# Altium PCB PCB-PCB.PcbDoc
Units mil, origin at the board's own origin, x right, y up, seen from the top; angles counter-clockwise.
Board outline 3937.01 x 1771.65 mil, 2 copper layers (Top Layer, Bottom Layer); 15 components, 36 nets, 117 pads, 7 vias.
Unrouted connection lines stored in the file: 2.
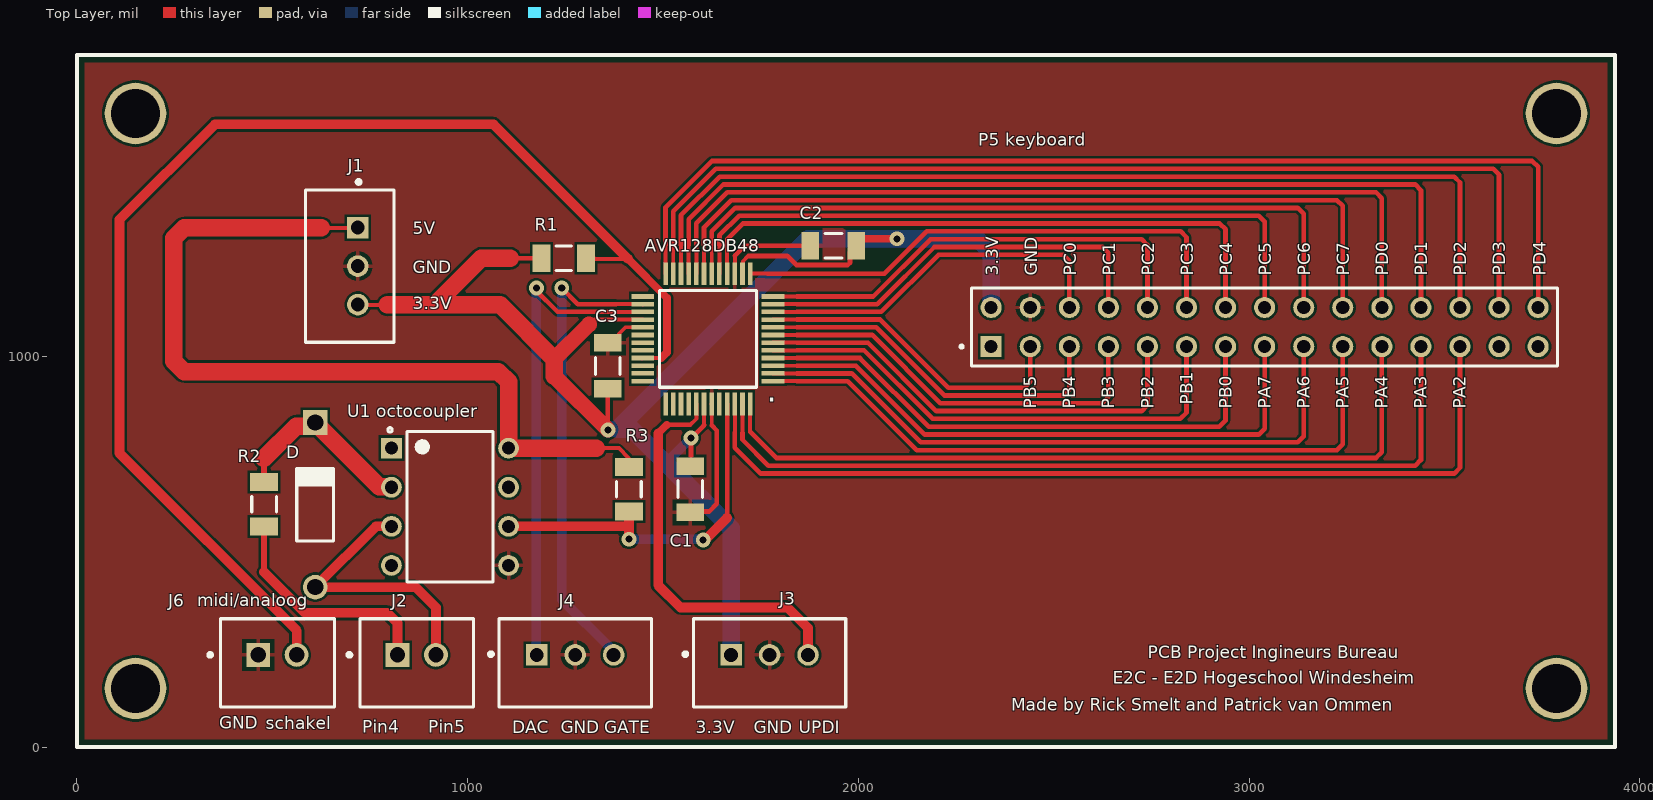
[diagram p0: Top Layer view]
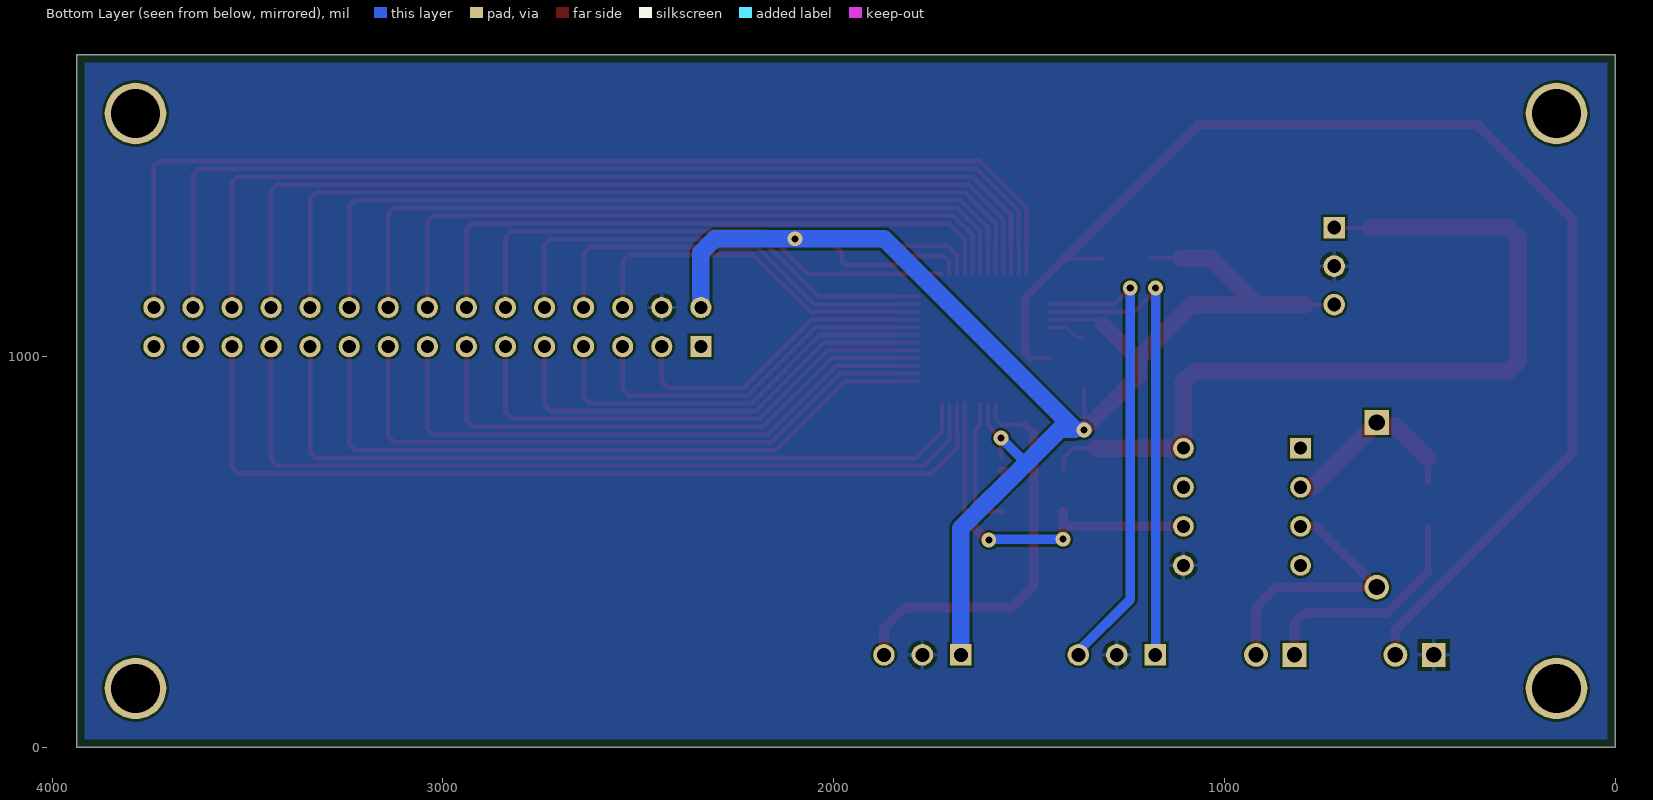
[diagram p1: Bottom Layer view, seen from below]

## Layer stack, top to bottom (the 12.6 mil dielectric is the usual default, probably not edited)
Top Solder: solder mask 0.4, Solder Resist, Dk 3.5
Top Layer: signal copper 1.4
Dielectric 1: dielectric 12.6, FR-4, Dk 4.8
Bottom Layer: signal copper 1.4
Bottom Solder: solder mask 0.4, Solder Resist, Dk 3.5

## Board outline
0,0 0,1771.65 3937.01,1771.65 3937.01,0

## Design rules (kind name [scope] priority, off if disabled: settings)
Clearance [All] p1: gap=6 ignorepadtopadclearanceinfootprint=TRUE
HoleSize [All] p1: absolutevalues=TRUE maxlimit=220.47 minlimit=12 maxpercent=80.000 minpercent=20.000
HoleToHoleClearance [All] p1: gap=12 allowstackedmicrovias=FALSE
MinimumAnnularRing [All] p1: minimumring=8
MinimumSolderMaskSliver [All] p1: minsoldermaskwidth=6
PolygonConnect [All] p1: connectstyle=Relief reliefconductorwidth=10 reliefentries=4 polygonreliefangle="90 Angle" airgapwidth=10
RoutingVias [All] p1: holewidth=18 width=26 viastyle="Through Hole" minholewidth=12 minwidth=26 maxholewidth=18 maxwidth=50
SilkToSolderMaskClearance [IsPad] p1: minsilkscreentomaskgap=6 clearancetoexposedcopper=TRUE
SolderMaskExpansion [All] p1: expansion=4 istentingtop=FALSE
SupplyNets "Schematic Supply Nets_1" [InNet('GND')] p1: voltage=0.000
Width [All] p1: maxlimit=45 minlimit=8 preferedwidth=10
26 further rules are at their usual default settings.

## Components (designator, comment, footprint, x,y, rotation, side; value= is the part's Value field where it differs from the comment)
AVR128DB48 "AVR128DB48-I_PT" QFP50P900X900X120-48N 1615,1045 r180 top
C1 "100nF" C1206 1570,660 r90 top
C2 "100nF" C1206 1936,1283 r0 top
C3 "100nF" C1206 1359,976 r270 top
D "IN4007" DIOAD1070W78L470D235P 610,620 r270 top
J1 "B3B-XH-A(LF)(SN)" FP-B3B-XH-A_LF_SN-MFG 698.33,1231 r270 top
J2 "B2B-XH-A(LF)(SN)" FP-B2B-XH-A_LF_SN-MFG 869.79,215.33 r0 top
J3 "B3B-XH-A(LF)(SN)" FP-B3B-XH-A_LF_SN-MFG 1773,215.33 r0 top
J4 "B3B-XH-A(LF)(SN)" FP-B3B-XH-A_LF_SN-MFG 1275.43,215.33 r0 top
J6 "B2B-XH-A(LF)(SN)" FP-B2B-XH-A_LF_SN-MFG 513.21,215.33 r0 top
"P5 keyboard" "TSW-115-14-S-D" SAMTEC_TSW-115-14-S-D 2340,1025 r0 top
R1 "10k" R1206 1246,1251 r0 top
R2 "220" R1206 479,621.48 r90 top
R3 "1K" R1206 1413,660 r270 top
"U1 octocoupler" "6N139VM" DIP762W50P254L977H451Q8 955,615 r0 top

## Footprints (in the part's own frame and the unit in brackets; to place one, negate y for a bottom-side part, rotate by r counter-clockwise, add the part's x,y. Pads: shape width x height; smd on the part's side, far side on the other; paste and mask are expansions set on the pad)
C1206 [mm] "Chip Capacitor, Body 3.2x1.6mm, Height 1.7mm, IPC Medium Density"
  rect 1.15x1.8 smd: 1(-1.5,0) 2(1.5,0)
  silkscreen extent -0.55,-0.8 0.55,0.8, body extent -1.7,-0.9 1.7,0.9, height 1.7
DIOAD1070W78L470D235P [mm]
  round 1.6 hole 1.05: A(5.35,0)
  rect 1.6x1.6 hole 1.05: C(-5.35,0)
  silkscreen extent -2.4,-1.2 2.35,1.2
DIP762W50P254L977H451Q8 [mm]
  rect 1.35x1.35 hole 0.85: 1(-3.81,3.81)
  round 1.35 hole 0.85: 2(-3.81,1.27) 3(-3.81,-1.27) 4(-3.81,-3.81) 5(3.81,-3.81) 6(3.81,-1.27) 7(3.81,1.27) 8(3.81,3.81)
  silkscreen extent -4.04,-4.9 2.8,5.14
FP-B2B-XH-A_LF_SN-MFG [mm]
  rect 1.55x1.55 hole 1 paste-2539.97 mask+0: 1(-1.25,0.525)
  round 1.55 hole 1 paste-2539.97 mask+0: 2(1.25,0.525)
  silkscreen extent -4.5,-2.88 3.7,2.88, body extent -3.8,-2.98 3.8,2.98, height 0.25
FP-B3B-XH-A_LF_SN-MFG [mm]
  rect 1.4x1.4 hole 0.9 paste-2539.97 mask+0: 1(-2.5,0.525)
  round 1.4 hole 0.9 paste-2539.97 mask+0: 2(0,0.525) 3(2.5,0.525)
  silkscreen extent -5.6,-2.88 4.95,2.88, body extent -5.05,-2.98 5.05,2.98, height 0.25
QFP50P900X900X120-48N [mm]
  rect 1.475x0.3 smd: 1(-4.238,2.75) 2(-4.238,2.25) 3(-4.238,1.75) 4(-4.238,1.25) 5(-4.238,0.75) 6(-4.238,0.25) 7(-4.238,-0.25) 8(-4.238,-0.75) 9(-4.238,-1.25) 10(-4.238,-1.75) 11(-4.238,-2.25) 12(-4.238,-2.75) 25(4.238,-2.75) 26(4.238,-2.25) 27(4.238,-1.75) 28(4.238,-1.25) 29(4.238,-0.75) 30(4.238,-0.25) 31(4.238,0.25) 32(4.238,0.75) 33(4.238,1.25) 34(4.238,1.75) 35(4.238,2.25) 36(4.238,2.75)
  rect 0.3x1.475 smd: 13(-2.75,-4.238) 14(-2.25,-4.238) 15(-1.75,-4.238) 16(-1.25,-4.238) 17(-0.75,-4.238) 18(-0.25,-4.238) 19(0.25,-4.238) 20(0.75,-4.238) 21(1.25,-4.238) 22(1.75,-4.238) 23(2.25,-4.238) 24(2.75,-4.238) 37(2.75,4.238) 38(2.25,4.238) 39(1.75,4.238) 40(1.25,4.238) 41(0.75,4.238) 42(0.25,4.238) 43(-0.25,4.238) 44(-0.75,4.238) 45(-1.25,4.238) 46(-1.75,4.238) 47(-2.25,4.238) 48(-2.75,4.238)
  silkscreen extent -3.15,-3.15 3.15,3.15
R1206 [mm] "Chip Resistor, Body 3.2x1.6mm, IPC Medium Density"
  rect 1.15x1.8 smd: 1(-1.45,0) 2(1.45,0)
  silkscreen extent -0.5,-0.8 0.5,0.8, body extent -1.67,-0.87 1.67,0.87, height 0.75
SAMTEC_TSW-115-14-S-D [mm]
  rect 1.37x1.37 hole 0.85: 01(0,0)
  round 1.37 hole 0.85: 02(0,2.54) 03(2.54,0) 04(2.54,2.54) 05(5.08,0) 06(5.08,2.54) 07(7.62,0) 08(7.62,2.54) 09(10.16,0) 10(10.16,2.54) 11(12.7,0) 12(12.7,2.54) 13(15.24,0) 14(15.24,2.54) 15(17.78,0) 16(17.78,2.54) 17(20.32,0) 18(20.32,2.54) 19(22.86,0) 20(22.86,2.54) 21(25.4,0) 22(25.4,2.54) 23(27.94,0) 24(27.94,2.54) 25(30.48,0) 26(30.48,2.54) 27(33.02,0) 28(33.02,2.54) 29(35.56,0) 30(35.56,2.54)
  silkscreen extent -2.02,-1.27 36.83,3.81

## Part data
AVR128DB48: "AVR AVRÂ® DB Microcontroller IC 8-Bit 24MHz 128KB (128K x 8) FLASH 48-TQFP (7x7)", Package=None
C1 C2 C3: library part Capacitor_1206, "SMD Capacitor 1206"
D: "Diode Standard 1000V 1A Through Hole DO-204AL _DO-41_", Package="DO-41 Vishay"
J1 J3 J4: library part CMP-17439-000014-3, "CONN HEADER VERT 3POS 2.5MM", Color=Natural, Contact Resistance=20mR, Current Rating=3A, Flammability Rating="UL94 V-0", Housing Color=White, Insulation Resistance=1GR, Max Operating Temperature=85°C, Max Voltage Rating (AC)=250V, Min Operating Temperature=-25°C
J2 J6: library part CMP-2000-05888-3, "CONN HEADER VERT 2POS 2.5MM", Color=Natural, Contact Resistance=20mR, Current Rating=3A, Housing Color=White, Insulation Resistance=1GR, Max Operating Temperature=85°C, Max Voltage Rating (AC)=250V, Min Operating Temperature=-25°C
"P5 keyboard": Package=None
R1 R2 R3: library part Resistor_1206, "SMD Resistor 1206"
"U1 octocoupler": "High Speed Optocoupler, 100 kBd, Low Input Current, Photodiode Darlington Output", Package=None

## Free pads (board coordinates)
  round 157.48 hole 125.98: 2(3787.01,1621.65) 3(3787.01,150) 4(150,150) 5(150,1621.65)

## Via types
v1: diameter 38, hole 18, Top Layer to Bottom Layer, 7 vias

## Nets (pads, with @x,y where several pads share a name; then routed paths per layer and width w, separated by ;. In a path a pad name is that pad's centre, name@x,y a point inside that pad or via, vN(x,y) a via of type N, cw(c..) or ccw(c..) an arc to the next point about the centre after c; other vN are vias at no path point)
GND: "P5 keyboard.04" "U1 octocoupler.5" AVR128DB48.15 AVR128DB48.29 AVR128DB48.43 C1.1 C2.1 C3.1 J1.2 J3.2 J4.2 J6.1 | length 686.1
  Top Layer w8: C3.1@1363,1043.63 1368.73,1049.36 1379.36,1049.36 C3.1@1386.86,1056.86
  Top Layer w10: C3.1@1386.86,1056.86 1404.53,1074.53 AVR128DB48.29 ; 1624.84,823.16 AVR128DB48.43 ; AVR128DB48.15 1683.9,1257.58
  Top Layer w12: C1.1@1567.94,603 1618,603 1637.73,622.73 1637.73,810.27 1624.84,823.16 ; AVR128DB48.43 AVR128DB48.43@1624.94,878.06 ; 1683.9,1257.58 1709.31,1283 C2.1
NetAVR128DB48_1: "P5 keyboard.19" AVR128DB48.1 | length 1787.6
  Top Layer w10: AVR128DB48.1 1843,936.73
  Top Layer w12: 1843,936.73 1973.27,936.73 2150,760 3225,760 3240,775 3240,1025
NetAVR128DB48_2: "P5 keyboard.17" AVR128DB48.2 | length 1667.4
  Top Layer w10: AVR128DB48.2 1843,956.42
  Top Layer w12: 1843,956.42 1983.58,956.42 2160,780 3125,780 3140,795 3140,1025
NetAVR128DB48_3: "P5 keyboard.15" AVR128DB48.3 | length 1547.3
  Top Layer w10: AVR128DB48.3 1843,976.1
  Top Layer w12: 1843,976.1 1993.9,976.1 2170,800 3025,800 3040,815 3040,1025
NetAVR128DB48_4: "P5 keyboard.13" AVR128DB48.4 | length 1426.6
  Top Layer w10: AVR128DB48.4 1843,995.79
  Top Layer w12: 1843,995.79 2004.21,995.79 2180,820 2924,820 2940,836 2940,1025
NetAVR128DB48_5: "P5 keyboard.11" AVR128DB48.5 | length 1306.5
  Top Layer w10: AVR128DB48.5 1843,1015.47
  Top Layer w12: 1843,1015.47 2014.53,1015.47 2190,840 2824,840 2840,856 2840,1025
NetAVR128DB48_6: "P5 keyboard.09" AVR128DB48.6 | length 1186.9
  Top Layer w10: AVR128DB48.6 1843,1035.16
  Top Layer w12: 1843,1035.16 2024.84,1035.16 2200,860 2725,860 2740,875 2740,1025
NetAVR128DB48_7: "P5 keyboard.07" AVR128DB48.7 | length 1066.2
  Top Layer w10: AVR128DB48.7 1843,1054.84
  Top Layer w12: 1843,1054.84 2035.16,1054.84 2210,880 2624,880 2640,896 2640,1025
NetAVR128DB48_8: "P5 keyboard.05" AVR128DB48.8 | length 946.7
  Top Layer w10: AVR128DB48.8 1843,1074.53
  Top Layer w12: 1843,1074.53 2045.47,1074.53 2220,900 2525,900 2540,915 2540,1025
NetAVR128DB48_9: "P5 keyboard.03" AVR128DB48.9 | length 826.5
  Top Layer w10: AVR128DB48.9 1843,1094.21
  Top Layer w12: 1843,1094.21 2055.79,1094.21 2230,920 2425,920 2440,935 2440,1025
NetAVR128DB48_10: "P5 keyboard.06" AVR128DB48.10 | length 945.2
  Top Layer w10: AVR128DB48.10 1843,1113.9
  Top Layer w12: 1843,1113.9 2058.9,1113.9 2205.34,1260.34 2524.66,1260.34 2540,1245 2540,1125
NetAVR128DB48_11: "P5 keyboard.08" AVR128DB48.11 | length 1065
  Top Layer w10: AVR128DB48.11 1843,1133.58
  Top Layer w12: 1843,1133.58 2048.58,1133.58 2195,1280 2625,1280 2640,1265 2640,1125
NetAVR128DB48_12: "P5 keyboard.10" AVR128DB48.12 | length 1185.1
  Top Layer w10: AVR128DB48.12 1843,1153.27
  Top Layer w12: 1843,1153.27 2038.27,1153.27 2185,1300 2725,1300 2740,1285 2740,1125
NetAVR128DB48_13: "P5 keyboard.12" AVR128DB48.13 | length 1347.7
  Top Layer w10: AVR128DB48.13 1767,1211.85
  Top Layer w12: 1767,1211.85 2066.85,1211.85 2175,1320 2825,1320 2840,1305 2840,1125
NetAVR128DB48_14: "P5 keyboard.02" AVR128DB48.14 AVR128DB48.28 AVR128DB48.42 C1.2 C2.2 C3.2 J1.3 J3.1 R1.1 | length 4299.6
  Top Layer w8: 1082.78,1132.22 1084.67,1130.33
  Top Layer w10: J1.3@709,1132 795,1132 ; 1310.64,1081.64 1311.82,1081.64 1324.39,1094.21 1376.92,1094.21 AVR128DB48.28 ; 1605.16,824.16 AVR128DB48.42 ; AVR128DB48.14 1704.49,1212.76 1704.49,1243.57 1717.92,1257 ; C2.2@1978.91,1266.86 C2.2
  Top Layer w12: 1109,1251 R1.1 ; v1(1359,812) C3.2 ; 1572,744 v1(1572,791) 1605.16,824.16 ; 1717.92,1257 1818,1257 1841,1234 1949.15,1234 1973.06,1234 1978.91,1239.86 C2.2@1978.91,1266.86
  Top Layer w20: C1.2@1557.36,706.42 1568.42,706.42 C1.2@1570,708 ; C2.2 1995.06,1288.36 2007.69,1301 v1(2099,1301)
  Top Layer w40: 1222,949 v1(1359,812) ; 1222,993 1310.64,1081.64
  Top Layer w45: 795,1132 795.33,1132.33 916.33,1132.33 ; 1082.89,1132.33 916.33,1132.33 ; 1084.67,1130.33 1222,993 1222,949 ; 1109,1251 1035,1251 916.33,1132.33
  Bottom Layer w12: 1507.43,726.57 1507.57,726.57
  Bottom Layer w25: 1507.57,726.57 v1(1572,791)
  Bottom Layer w40: v1(1359,812) 1360.15,813.15 1383.15,813.15
  Bottom Layer w45: J3.1@1676,241.06 1674.57,241.06 1674.57,560.43 1595,640 1594,640 1507.43,726.57 1420.85,813.15 1383.15,813.15 1871,1301 v1(2099,1301) 2304,1301 2340,1265 2340,1125
NetAVR128DB48_16: "P5 keyboard.14" AVR128DB48.16 | length 1586.8
  Top Layer w10: AVR128DB48.16 1664.21,1285
  Top Layer w12: 1664.21,1285 1664.21,1300.21 1704,1340 2925,1340 2940,1325 2940,1125
NetAVR128DB48_17: "P5 keyboard.16" AVR128DB48.17 | length 1740.3
  Top Layer w10: AVR128DB48.17 1644.53,1285
  Top Layer w12: 1644.53,1285 1644.53,1309.53 1695,1360 3025,1360 3040,1345 3040,1125
NetAVR128DB48_18: "P5 keyboard.18" AVR128DB48.18 | length 1894.3
  Top Layer w10: AVR128DB48.18 1624.84,1285
  Top Layer w12: 1624.84,1285 1624.84,1319.84 1685,1380 3125,1380 3140,1365 3140,1125
NetAVR128DB48_19: "P5 keyboard.20" AVR128DB48.19 | length 2048.3
  Top Layer w10: AVR128DB48.19 1605.16,1285
  Top Layer w12: 1605.16,1285 1605.16,1330.16 1675,1400 3225,1400 3240,1385 3240,1125
NetAVR128DB48_20: "P5 keyboard.22" AVR128DB48.20 | length 2202.3
  Top Layer w10: AVR128DB48.20 1585.47,1285
  Top Layer w12: 1585.47,1285 1585.47,1340.47 1665,1420 3325,1420 3340,1405 3340,1125
NetAVR128DB48_21: "P5 keyboard.24" AVR128DB48.21 | length 2356.3
  Top Layer w10: AVR128DB48.21 1565.79,1285
  Top Layer w12: 1565.79,1285 1565.79,1350.79 1655,1440 3425,1440 3440,1425 3440,1125
NetAVR128DB48_22: "P5 keyboard.26" AVR128DB48.22 | length 2510.3
  Top Layer w10: AVR128DB48.22 1546.1,1285
  Top Layer w12: 1546.1,1285 1546.1,1361.1 1645,1460 3525,1460 3540,1445 3540,1125
NetAVR128DB48_23: "P5 keyboard.28" AVR128DB48.23 | length 2664.3
  Top Layer w10: AVR128DB48.23 1526.42,1285
  Top Layer w12: 1526.42,1285 1526.42,1371.42 1635,1480 3625,1480 3640,1465 3640,1125
NetAVR128DB48_24: "P5 keyboard.30" AVR128DB48.24 | length 2818.4
  Top Layer w10: AVR128DB48.24 1506.73,1285
  Top Layer w12: 1506.73,1285 1506.73,1381.73 1625,1500 3725,1500 3740,1485 3740,1125
NetAVR128DB48_26: AVR128DB48.26 J4.3 | length 1210
  Top Layer w10: 1380.6,1133.58 AVR128DB48.26
  Top Layer w12: v1(1241,1175) 1282.41,1133.59 1380.59,1133.59 ; AVR128DB48.26@1448.06,1133.68 AVR128DB48.26
  Bottom Layer w25: v1(1241,1175) 1241,377.85 1368.09,250.76 1368.09,249.91 1373,245 J4.3@1373.85,245
NetAVR128DB48_27: AVR128DB48.27 J4.1 | length 1241
  Top Layer w10: 1373.9,1113.9 AVR128DB48.27
  Top Layer w12: v1(1176,1175) 1176,1168 1230.1,1113.9 1373.9,1113.9
  Bottom Layer w12: J4.1@1176,237 J4.1
  Bottom Layer w25: J4.1@1176,237 v1(1176,1175)
NetAVR128DB48_33: AVR128DB48.33 J6.2 R1.2 | length 3298.3
  Top Layer w8: R1.2@1321,1251 R1.2@1322.4,1249.6 ; AVR128DB48.33@1446.24,993.88 AVR128DB48.33
  Top Layer w10: R1.2@1310,1251 1321,1251 R1.2@1324.86,1251 ; R1.2@1322.4,1249.6 1410.4,1249.6 ; AVR128DB48.33 1495.79,995.79
  Top Layer w20: 1410.4,1249.6 1510,1150 1510,1010 1495.79,995.79
  Top Layer w25: J6.2@563,241 563,298 109,752 109,1350 353,1594 1066,1594 1410.4,1249.6
NetAVR128DB48_41: AVR128DB48.41 J3.3 | length 1037
  Top Layer w10: 1569.69,824.69 1585.47,840.47 AVR128DB48.41
  Top Layer w12: 1509.69,824.69 1569.69,824.69
  Top Layer w20: 1488,803 1509.69,824.69
  Top Layer w25: 1488,803 1488,414 1545,357 1819,357 1871.43,304.57 J3.3
NetAVR128DB48_45: "U1 octocoupler.6" AVR128DB48.45 R3.2 | length 982.6
  Top Layer w12: 1411,565 1413,567 R3.2 ; 1664.21,586.79 AVR128DB48.45
  Top Layer w25: 1105,565 1411,565 ; v1(1413,532) 1413,567 R3.2 ; v1(1603,530) 1606.52,530 1613.02,536.5 1613.93,536.5 1664.21,586.79
  Bottom Layer w12: v1@1601,532 v1(1603,530)
  Bottom Layer w25: v1(1413,532) v1@1601,532
NetAVR128DB48_46: "P5 keyboard.25" AVR128DB48.46 | length 2311.7
  Top Layer w10: 1683.9,805 AVR128DB48.46
  Top Layer w12: 1683.9,805 1683.9,766.1 1750,700 3525,700 3540,715 3540,1025
NetAVR128DB48_47: "P5 keyboard.23" AVR128DB48.47 | length 2151.9
  Top Layer w10: 1703.58,804 AVR128DB48.47
  Top Layer w12: 1703.58,804 1703.58,786.42 1770,720 3425,720 3440,735 3440,1025
NetAVR128DB48_48: "P5 keyboard.21" AVR128DB48.48 | length 1992
  Top Layer w10: 1723.27,806.73 AVR128DB48.48
  Top Layer w12: 1723.27,806.73 1790,740 3325,740 3340,755 3340,1025
NetD_A: "U1 octocoupler.3" D.A J2.2 | length 703.7
  Top Layer w25: 802.54,565 765.63,565 D.A 866.63,409.37 919,357 J2.2@919,241
NetD_C: "U1 octocoupler.2" D.C R2.2 | length 493
  Top Layer w15: R2.2 479,739.01
  Top Layer w45: 479,739.01 561.62,821.63 601,821.63 D.C 774.07,666.56 803.44,666.56 805,665
NetJ1_1: "U1 octocoupler.8" J1.1 R3.1 | length 2180.9
  Top Layer w10: 625.15,1328.85 J1.1@709,1328.85 ; 1329,765 1387,765 1412,740 R3.1@1412,712
  Top Layer w45: 625.15,1328.85 274.36,1328.85 248,1302.49 248,987.36 274.36,961 1078.64,961 1105,934.64 1105,765 1329,765
NetJ2_1: J2.1 R2.1 | length 588.5
  Top Layer w15: 479,448 R2.1
  Top Layer w25: 479,448 583,344 794,344 820.57,317.43 J2.1@820.57,241
pads on no net: "P5 keyboard.01" "P5 keyboard.27" "P5 keyboard.29" "U1 octocoupler.1" "U1 octocoupler.4" "U1 octocoupler.7" AVR128DB48.25 AVR128DB48.30 AVR128DB48.31 AVR128DB48.32 AVR128DB48.34 AVR128DB48.35 AVR128DB48.36 AVR128DB48.37 AVR128DB48.38 AVR128DB48.39 AVR128DB48.40 AVR128DB48.44

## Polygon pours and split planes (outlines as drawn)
GND on Bottom Layer "Bottom Layer-GND" (solid, remove dead copper, pour order 0): 3917.01,1751.65 3917.01,20 20,20 20,1751.65
GND on Top Layer "GND_L01_P001" (solid, remove dead copper, pour order 1): 3917.01,1751.65 3917.01,20 20,20 20,1751.65

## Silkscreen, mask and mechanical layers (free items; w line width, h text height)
Top Overlay:
  the board outline again, w10
  text "5V" at 859,1313 h32
  text "GND" at 859,1213 h32
  text "3.3V" at 2358,1207 h32 r90
  text "GND" at 2457.86,1207 h32 r90
  text "PC0" at 2557.71,1207 h32 r90
  text "PC1" at 2657.57,1207 h32 r90
  text "PC2" at 2757.43,1207 h32 r90
  text "PC3" at 2857.29,1207 h32 r90
  text "PC4" at 2957.14,1207 h32 r90
  text "PC5" at 3057,1207 h32 r90
  text "PC6" at 3156.86,1207 h32 r90
  text "PC7" at 3256.71,1207 h32 r90
  text "PD0" at 3356.57,1207 h32 r90
  text "PD1" at 3456.43,1207 h32 r90
  text "PD2" at 3556.29,1207 h32 r90
  text "PD3" at 3656.14,1207 h32 r90
  text "PD4" at 3759,1207 h32 r90
  text "3.3V" at 859,1120 h32
  text "." at 1766,884 h60
  text "PB1" at 2855.38,876.66 h32 r90
  text "PB5" at 2456,866 h32 r90
  text "PB4" at 2555.85,866 h32 r90
  text "PB3" at 2655.69,866 h32 r90
  text "PB2" at 2755.54,866 h32 r90
  text "PB0" at 2955.23,866 h32 r90
  text "PA7" at 3055.08,866 h32 r90
  text "PA6" at 3154.92,866 h32 r90
  text "PA5" at 3254.77,866 h32 r90
  text "PA4" at 3354.61,866 h32 r90
  text "PA3" at 3454.46,866 h32 r90
  text "PA2" at 3554.31,866 h32 r90
  text "midi/analoog" at 308,360.34 h32
  text "PCB Project Ingineurs Bureau" at 2741,227.66 h32
  text "E2C - E2D Hogeschool Windesheim" at 2651,162.66 h32
  text "Made by Rick Smelt and Patrick van Ommen" at 2391,92.66 h32
  text "GND" at 364,47 h32
  text "schakel" at 484,46 h32
  text "Pin4" at 731,37 h32
  text "Pin5" at 899,37 h32
  text "DAC" at 1114,36 h32
  text "GND" at 1238,36 h32
  text "GATE" at 1350,36 h32
  text "3.3V" at 1584,36 h32
  text "GND" at 1732,36 h32
  text "UPDI" at 1847,36 h32
Mechanical 1:
  lines w10: 0,1760 0,0 ; 0,0 3937.01,0 3937.01,1771.65 0,1771.65 0,0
